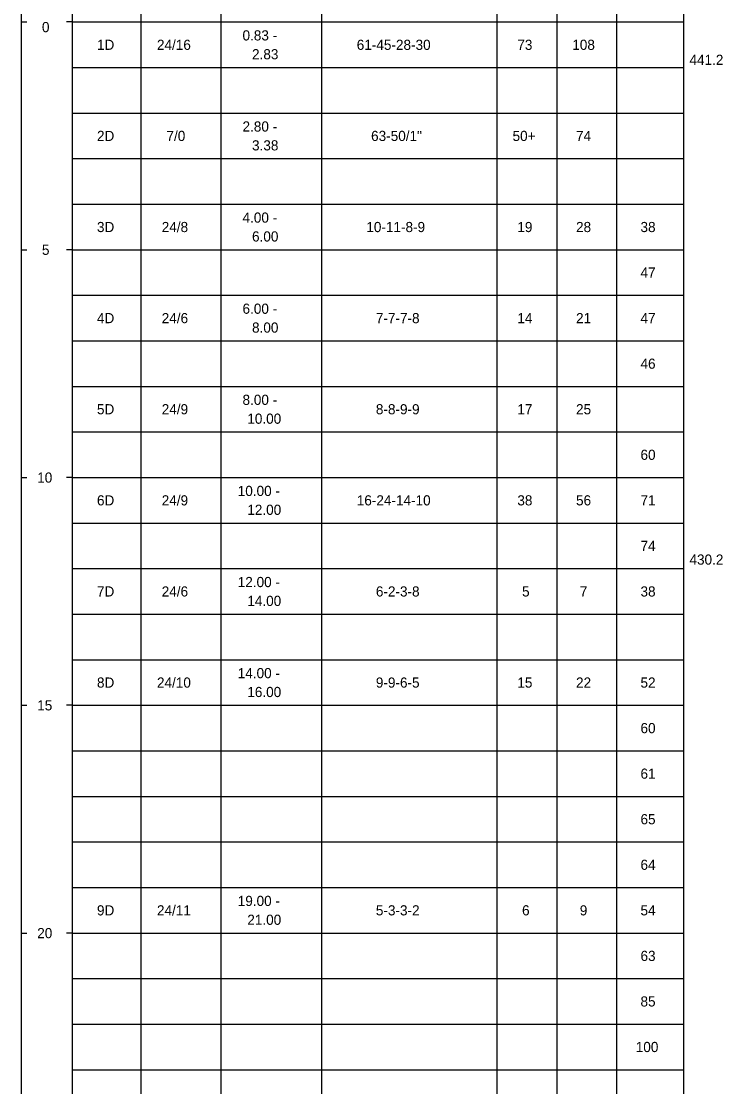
# Model space of a CAD drawing. Extents: x 9422 to 9552, y 6780 to 6860.
# Drawn here: x 9460.28 to 9475.69, y 6823.64 to 6847.03 of the extents above; entities that cross this region are included whole.
import ezdxf

# ---------------------------------------------------------------- set-up
doc = ezdxf.new("R2010")
doc.units = 0
doc.layers.add('7', color=7, linetype='Continuous')

msp = doc.modelspace()

# ---------------------------------------------------------------- linework, layer by layer
at = {"layer": '7'}
for points in [[(9460.282, 6860.114), (9460.282, 6821.983)], [(9461.4, 6850.528), (9461.4, 6821.983)], [(9462.909, 6849.992), (9462.909, 6821.983)], [(9464.665, 6849.992), (9464.665, 6821.983)], [(9466.879, 6849.992), (9466.879, 6821.983)], [(9470.734, 6849.992), (9470.734, 6821.983)], [(9472.046, 6849.992), (9472.046, 6821.983)], [(9473.359, 6849.992), (9473.359, 6821.983)], [(9474.835, 6849.992), (9474.835, 6821.983)], [(9460.282, 6847.011), (9460.404, 6847.011)], [(9461.4, 6847.011), (9461.279, 6847.011)], [(9461.4, 6847.011), (9462.909, 6847.011)], [(9462.909, 6847.011), (9464.665, 6847.011)], [(9464.665, 6847.011), (9466.879, 6847.011)], [(9466.879, 6847.011), (9470.734, 6847.011)], [(9470.734, 6847.011), (9472.046, 6847.011)], [(9472.046, 6847.011), (9473.359, 6847.011)], [(9473.359, 6847.011), (9474.835, 6847.011)], [(9461.4, 6846.011), (9462.909, 6846.011)], [(9462.909, 6846.011), (9464.665, 6846.011)], [(9464.665, 6846.011), (9466.879, 6846.011)], [(9466.879, 6846.011), (9470.734, 6846.011)], [(9470.734, 6846.011), (9472.046, 6846.011)], [(9472.046, 6846.011), (9473.359, 6846.011)], [(9473.359, 6846.011), (9474.835, 6846.011)], [(9461.4, 6845.011), (9462.909, 6845.011)], [(9462.909, 6845.011), (9464.665, 6845.011)], [(9464.665, 6845.011), (9466.879, 6845.011)], [(9466.879, 6845.011), (9470.734, 6845.011)], [(9470.734, 6845.011), (9472.046, 6845.011)], [(9472.046, 6845.011), (9473.359, 6845.011)], [(9473.359, 6845.011), (9474.835, 6845.011)], [(9461.4, 6844.011), (9462.909, 6844.011)], [(9462.909, 6844.011), (9464.665, 6844.011)], [(9464.665, 6844.011), (9466.879, 6844.011)], [(9466.879, 6844.011), (9470.734, 6844.011)], [(9470.734, 6844.011), (9472.046, 6844.011)], [(9472.046, 6844.011), (9473.359, 6844.011)], [(9473.359, 6844.011), (9474.835, 6844.011)], [(9461.4, 6843.011), (9462.909, 6843.011)], [(9462.909, 6843.011), (9464.665, 6843.011)], [(9464.665, 6843.011), (9466.879, 6843.011)], [(9466.879, 6843.011), (9470.734, 6843.011)], [(9470.734, 6843.011), (9472.046, 6843.011)], [(9472.046, 6843.011), (9473.359, 6843.011)], [(9473.359, 6843.011), (9474.835, 6843.011)], [(9460.282, 6842.011), (9460.404, 6842.011)], [(9461.4, 6842.011), (9461.279, 6842.011)], [(9461.4, 6842.011), (9462.909, 6842.011)], [(9462.909, 6842.011), (9464.665, 6842.011)], [(9464.665, 6842.011), (9466.879, 6842.011)], [(9466.879, 6842.011), (9470.734, 6842.011)], [(9470.734, 6842.011), (9472.046, 6842.011)], [(9472.046, 6842.011), (9473.359, 6842.011)], [(9473.359, 6842.011), (9474.835, 6842.011)], [(9461.4, 6841.011), (9462.909, 6841.011)], [(9462.909, 6841.011), (9464.665, 6841.011)], [(9464.665, 6841.011), (9466.879, 6841.011)], [(9466.879, 6841.011), (9470.734, 6841.011)], [(9470.734, 6841.011), (9472.046, 6841.011)], [(9472.046, 6841.011), (9473.359, 6841.011)], [(9473.359, 6841.011), (9474.835, 6841.011)], [(9461.4, 6840.011), (9462.909, 6840.011)], [(9462.909, 6840.011), (9464.665, 6840.011)], [(9464.665, 6840.011), (9466.879, 6840.011)], [(9466.879, 6840.011), (9470.734, 6840.011)], [(9470.734, 6840.011), (9472.046, 6840.011)], [(9472.046, 6840.011), (9473.359, 6840.011)], [(9473.359, 6840.011), (9474.835, 6840.011)], [(9461.4, 6839.011), (9462.909, 6839.011)], [(9462.909, 6839.011), (9464.665, 6839.011)], [(9464.665, 6839.011), (9466.879, 6839.011)], [(9466.879, 6839.011), (9470.734, 6839.011)], [(9470.734, 6839.011), (9472.046, 6839.011)], [(9472.046, 6839.011), (9473.359, 6839.011)], [(9473.359, 6839.011), (9474.835, 6839.011)], [(9461.4, 6838.011), (9462.909, 6838.011)], [(9462.909, 6838.011), (9464.665, 6838.011)], [(9464.665, 6838.011), (9466.879, 6838.011)], [(9466.879, 6838.011), (9470.734, 6838.011)], [(9470.734, 6838.011), (9472.046, 6838.011)], [(9472.046, 6838.011), (9473.359, 6838.011)], [(9473.359, 6838.011), (9474.835, 6838.011)], [(9460.282, 6837.011), (9460.404, 6837.011)], [(9461.4, 6837.011), (9461.279, 6837.011)], [(9461.4, 6837.011), (9462.909, 6837.011)], [(9462.909, 6837.011), (9464.665, 6837.011)], [(9464.665, 6837.011), (9466.879, 6837.011)], [(9466.879, 6837.011), (9470.734, 6837.011)], [(9470.734, 6837.011), (9472.046, 6837.011)], [(9472.046, 6837.011), (9473.359, 6837.011)], [(9473.359, 6837.011), (9474.835, 6837.011)], [(9461.4, 6836.011), (9462.909, 6836.011)], [(9462.909, 6836.011), (9464.665, 6836.011)], [(9464.665, 6836.011), (9466.879, 6836.011)], [(9466.879, 6836.011), (9470.734, 6836.011)], [(9470.734, 6836.011), (9472.046, 6836.011)], [(9472.046, 6836.011), (9473.359, 6836.011)], [(9473.359, 6836.011), (9474.835, 6836.011)], [(9461.4, 6835.011), (9462.909, 6835.011)], [(9462.909, 6835.011), (9464.665, 6835.011)], [(9464.665, 6835.011), (9466.879, 6835.011)], [(9466.879, 6835.011), (9470.734, 6835.011)], [(9470.734, 6835.011), (9472.046, 6835.011)], [(9472.046, 6835.011), (9473.359, 6835.011)], [(9473.359, 6835.011), (9474.835, 6835.011)], [(9461.4, 6834.011), (9462.909, 6834.011)], [(9462.909, 6834.011), (9464.665, 6834.011)], [(9464.665, 6834.011), (9466.879, 6834.011)], [(9466.879, 6834.011), (9470.734, 6834.011)], [(9470.734, 6834.011), (9472.046, 6834.011)], [(9472.046, 6834.011), (9473.359, 6834.011)], [(9473.359, 6834.011), (9474.835, 6834.011)], [(9461.4, 6833.011), (9462.909, 6833.011)], [(9462.909, 6833.011), (9464.665, 6833.011)], [(9464.665, 6833.011), (9466.879, 6833.011)], [(9466.879, 6833.011), (9470.734, 6833.011)], [(9470.734, 6833.011), (9472.046, 6833.011)], [(9472.046, 6833.011), (9473.359, 6833.011)], [(9473.359, 6833.011), (9474.835, 6833.011)], [(9460.282, 6832.011), (9460.404, 6832.011)], [(9461.4, 6832.011), (9461.279, 6832.011)], [(9461.4, 6832.011), (9462.909, 6832.011)], [(9462.909, 6832.011), (9464.665, 6832.011)], [(9464.665, 6832.011), (9466.879, 6832.011)], [(9466.879, 6832.011), (9470.734, 6832.011)], [(9470.734, 6832.011), (9472.046, 6832.011)], [(9472.046, 6832.011), (9473.359, 6832.011)], [(9473.359, 6832.011), (9474.835, 6832.011)], [(9461.4, 6831.011), (9462.909, 6831.011)], [(9462.909, 6831.011), (9464.665, 6831.011)], [(9464.665, 6831.011), (9466.879, 6831.011)], [(9466.879, 6831.011), (9470.734, 6831.011)], [(9470.734, 6831.011), (9472.046, 6831.011)], [(9472.046, 6831.011), (9473.359, 6831.011)], [(9473.359, 6831.011), (9474.835, 6831.011)], [(9461.4, 6830.011), (9462.909, 6830.011)], [(9462.909, 6830.011), (9464.665, 6830.011)], [(9464.665, 6830.011), (9466.879, 6830.011)], [(9466.879, 6830.011), (9470.734, 6830.011)], [(9470.734, 6830.011), (9472.046, 6830.011)], [(9472.046, 6830.011), (9473.359, 6830.011)], [(9473.359, 6830.011), (9474.835, 6830.011)], [(9461.4, 6829.011), (9462.909, 6829.011)], [(9462.909, 6829.011), (9464.665, 6829.011)], [(9464.665, 6829.011), (9466.879, 6829.011)], [(9466.879, 6829.011), (9470.734, 6829.011)], [(9470.734, 6829.011), (9472.046, 6829.011)], [(9472.046, 6829.011), (9473.359, 6829.011)], [(9473.359, 6829.011), (9474.835, 6829.011)], [(9461.4, 6828.011), (9462.909, 6828.011)], [(9462.909, 6828.011), (9464.665, 6828.011)], [(9464.665, 6828.011), (9466.879, 6828.011)], [(9466.879, 6828.011), (9470.734, 6828.011)], [(9470.734, 6828.011), (9472.046, 6828.011)], [(9472.046, 6828.011), (9473.359, 6828.011)], [(9473.359, 6828.011), (9474.835, 6828.011)], [(9460.282, 6827.011), (9460.404, 6827.011)], [(9461.4, 6827.011), (9461.279, 6827.011)], [(9461.4, 6827.011), (9462.909, 6827.011)], [(9462.909, 6827.011), (9464.665, 6827.011)], [(9464.665, 6827.011), (9466.879, 6827.011)], [(9466.879, 6827.011), (9470.734, 6827.011)], [(9470.734, 6827.011), (9472.046, 6827.011)], [(9472.046, 6827.011), (9473.359, 6827.011)], [(9473.359, 6827.011), (9474.835, 6827.011)], [(9461.4, 6826.011), (9462.909, 6826.011)], [(9462.909, 6826.011), (9464.665, 6826.011)], [(9464.665, 6826.011), (9466.879, 6826.011)], [(9466.879, 6826.011), (9470.734, 6826.011)], [(9470.734, 6826.011), (9472.046, 6826.011)], [(9472.046, 6826.011), (9473.359, 6826.011)], [(9473.359, 6826.011), (9474.835, 6826.011)], [(9461.4, 6825.011), (9462.909, 6825.011)], [(9462.909, 6825.011), (9464.665, 6825.011)], [(9464.665, 6825.011), (9466.879, 6825.011)], [(9466.879, 6825.011), (9470.734, 6825.011)], [(9470.734, 6825.011), (9472.046, 6825.011)], [(9472.046, 6825.011), (9473.359, 6825.011)], [(9473.359, 6825.011), (9474.835, 6825.011)], [(9461.4, 6824.011), (9462.909, 6824.011)], [(9462.909, 6824.011), (9464.665, 6824.011)], [(9464.665, 6824.011), (9466.879, 6824.011)], [(9466.879, 6824.011), (9470.734, 6824.011)], [(9470.734, 6824.011), (9472.046, 6824.011)], [(9472.046, 6824.011), (9473.359, 6824.011)], [(9473.359, 6824.011), (9474.835, 6824.011)]]:
    msp.add_lwpolyline(points, dxfattribs=at)

# ---------------------------------------------------------------- texts
for s, height, p in [('0', 0.223, (9460.736, 6846.788)), ('24/16', 0.2228, (9463.263, 6846.399)), ('0.83 -', 0.2228, (9465.143, 6846.606)), ('1D', 0.2228, (9461.945, 6846.399)), ('2.83', 0.2228, (9465.352, 6846.192)), ('61-45-28-30', 0.2228, (9467.653, 6846.399)), ('73', 0.2228, (9471.181, 6846.399)), ('108', 0.2228, (9472.388, 6846.399)), ('441.2', 0.2228, (9474.963, 6846.069)), ('2.80 -', 0.2228, (9465.143, 6844.606)), ('2D', 0.2228, (9461.945, 6844.399)), ('7/0', 0.2228, (9463.472, 6844.399)), ('63-50/1"', 0.2228, (9467.968, 6844.399)), ('50+', 0.2228, (9471.076, 6844.399)), (' 74', 0.2228, (9472.388, 6844.399)), ('3.38', 0.2228, (9465.352, 6844.192)), ('4.00 -', 0.2228, (9465.143, 6842.606)), ('3D', 0.2228, (9461.945, 6842.399)), ('24/8', 0.2228, (9463.368, 6842.399)), ('10-11-8-9', 0.2228, (9467.863, 6842.399)), ('19', 0.2228, (9471.181, 6842.399)), (' 28', 0.2228, (9472.388, 6842.399)), ('38', 0.2228, (9473.887, 6842.399)), ('6.00', 0.2228, (9465.352, 6842.192)), ('5', 0.223, (9460.736, 6841.899)), ('47', 0.2228, (9473.887, 6841.399)), ('6.00 -', 0.2228, (9465.143, 6840.606)), ('4D', 0.2228, (9461.945, 6840.399)), ('24/6', 0.2228, (9463.368, 6840.399)), ('7-7-7-8', 0.2228, (9468.073, 6840.399)), ('14', 0.2228, (9471.181, 6840.399)), (' 21', 0.2228, (9472.388, 6840.399)), ('47', 0.2228, (9473.887, 6840.399)), ('8.00', 0.2228, (9465.352, 6840.192)), ('46', 0.2228, (9473.887, 6839.399)), ('8.00 -', 0.2228, (9465.143, 6838.606)), ('5D', 0.2228, (9461.945, 6838.399)), ('24/9', 0.2228, (9463.368, 6838.399)), ('8-8-9-9', 0.2228, (9468.073, 6838.399)), ('17', 0.2228, (9471.181, 6838.399)), (' 25', 0.2228, (9472.388, 6838.399)), ('10.00', 0.2228, (9465.248, 6838.192)), ('60', 0.2228, (9473.887, 6837.399)), ('10', 0.2228, (9460.632, 6836.899)), ('10.00 -', 0.2228, (9465.038, 6836.606)), ('6D', 0.2228, (9461.945, 6836.399)), ('24/9', 0.2228, (9463.368, 6836.399)), ('16-24-14-10', 0.2228, (9467.653, 6836.399)), ('38', 0.2228, (9471.181, 6836.399)), (' 56', 0.2228, (9472.388, 6836.399)), ('71', 0.2228, (9473.887, 6836.399)), ('12.00', 0.2228, (9465.248, 6836.192)), ('74', 0.2228, (9473.887, 6835.399)), ('430.2', 0.2228, (9474.963, 6835.099)), ('12.00 -', 0.2228, (9465.038, 6834.606)), ('7D', 0.2228, (9461.945, 6834.399)), ('24/6', 0.2228, (9463.368, 6834.399)), ('6-2-3-8', 0.2228, (9468.073, 6834.399)), ('5', 0.223, (9471.285, 6834.399)), ('  7', 0.2228, (9472.388, 6834.399)), ('38', 0.2228, (9473.887, 6834.399)), ('14.00', 0.2228, (9465.248, 6834.192)), ('8D', 0.2228, (9461.945, 6832.399)), ('24/10', 0.2228, (9463.263, 6832.399)), ('14.00 -', 0.2228, (9465.038, 6832.606)), ('9-9-6-5', 0.2228, (9468.073, 6832.399)), ('15', 0.2228, (9471.181, 6832.399)), (' 22', 0.2228, (9472.388, 6832.399)), ('52', 0.2228, (9473.887, 6832.399)), ('16.00', 0.2228, (9465.248, 6832.192)), ('15', 0.2228, (9460.632, 6831.899)), ('60', 0.2228, (9473.887, 6831.399)), ('61', 0.2228, (9473.887, 6830.399)), ('65', 0.2228, (9473.887, 6829.399)), ('64', 0.2228, (9473.887, 6828.399)), ('19.00 -', 0.2228, (9465.038, 6827.606)), ('9D', 0.2228, (9461.945, 6827.399)), ('24/11', 0.2228, (9463.263, 6827.399)), ('5-3-3-2', 0.2228, (9468.073, 6827.399)), ('6', 0.223, (9471.285, 6827.399)), ('  9', 0.2228, (9472.388, 6827.399)), ('54', 0.2228, (9473.887, 6827.399)), ('21.00', 0.2228, (9465.248, 6827.192)), ('20', 0.2228, (9460.632, 6826.899)), ('63', 0.2228, (9473.887, 6826.399)), ('85', 0.2228, (9473.887, 6825.399)), ('100', 0.2228, (9473.783, 6824.399))]:
    msp.add_text(s, height=height, dxfattribs=at).set_placement(p)

doc.saveas('drawing.dxf')
